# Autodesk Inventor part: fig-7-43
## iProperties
Shininess: 77.0
Length Units: 11269
Angle Units: 11279
Time Units: 11290
Mass Units: 11283
Length Display Precision: 3
Angle Display Precision: 2
Created: 2002-01
Part Number: fig-7-43
Document SubType Name: Modeling
Designer: ***
Density: 0.0
Volumn: 0.0
Area: 0.0
PropertySet Name: Model Information
Control State: 0
Master: False
Checked Out: False
Author: ***
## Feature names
1. Extrusion1
2. Shell2
